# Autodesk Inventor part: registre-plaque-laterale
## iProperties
Author: chr
Shininess: 21.0
PropertySet Name: _Private Model Information
Length Units: 11269
Angle Units: 11286
Time Units: 11279
Mass Units: 11290
Length Display Precision: 3
Angle Display Precision: 2
Compacted: False
Created: 2001-06
Part Number: registre-plaque-laterale
Material: Par défaut
Document SubType Name: Tôlerie
Designer: chr
Control State: 0
Master: False
Checked Out: False
PropertySet Name: Design Tracking Control
Density: 0.0
Volumn: 0.0
Area: 0.0
PropertySet Name: Model Information
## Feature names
1. Ouverture1
2. Ouverture2
3. Ouverture3
4. Ouverture4
5. Perçage1 [Hole]
6. Réseau rectangulaire1 [Rectangular Pattern]
7. Ouverture5
8. Réseau circulaire1 [Circular Pattern]
9. Plaque1
